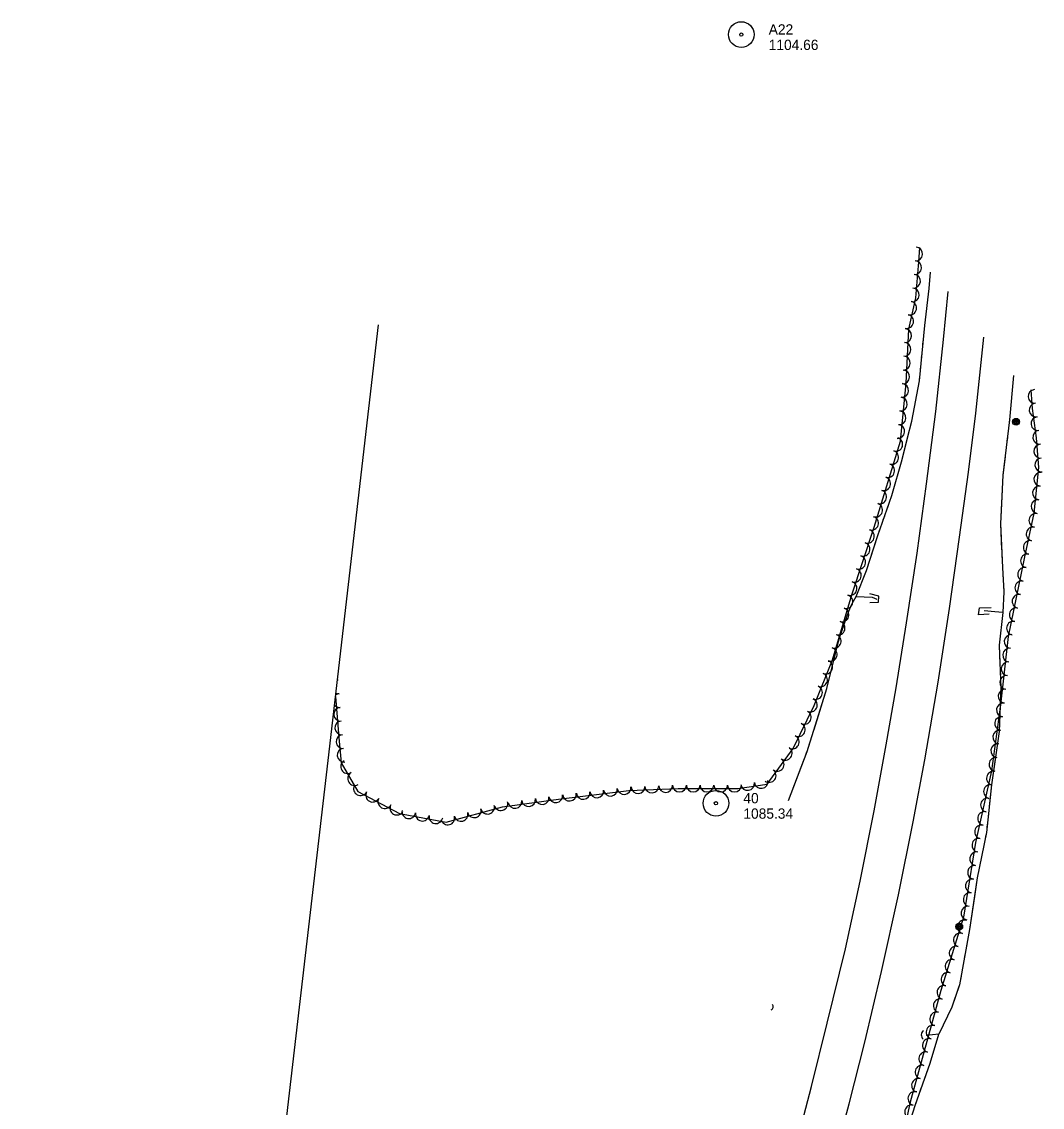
# Model space of a CAD drawing. Extents: x 296807 to 298965, y 28597 to 31038.
# Drawn here: x 297186 to 297782, y 30405 to 31038 of the extents above; entities that cross this region are included whole.
import ezdxf

# ---------------------------------------------------------------- set-up
doc = ezdxf.new("R2010")
doc.units = 0
for name, color, linetype in [('Level 11', 7, 'Continuous'), ('Level 14', 7, 'Continuous'), ('Level 15', 7, 'Continuous'), ('Level 18', 7, 'Continuous'), ('Level 19', 7, 'Continuous'), ('Level 4', 7, 'Continuous'), ('Level 6', 7, 'Continuous')]:
    doc.layers.add(name, color=color, linetype=linetype)

msp = doc.modelspace()

# ---------------------------------------------------------------- linework, layer by layer
at = {"layer": 'Level 11'}
for points in [[(297635.16, 30371.8), (297647.12, 30416.96), (297656.29, 30453.93), (297666.9, 30497.33), (297675.45, 30536.82), (297683.72, 30577.83), (297690.69, 30616.35), (297696.51, 30649.69), (297702.5, 30687.56), (297708.83, 30728.12), (297714.29, 30768.62), (297719.57, 30810.81), (297724.1, 30852.77), (297726.91, 30880.84)], [(297660.56, 30374.97), (297669.04, 30406.87), (297678.19, 30442.96), (297687.99, 30484.12), (297697.88, 30528.81), (297706.45, 30571.48), (297713.28, 30607.61), (297720.96, 30652.98), (297727.58, 30695.82), (297733.46, 30737.44), (297738.69, 30775.35), (297742.95, 30809.84), (297747.72, 30854.12)]]:
    msp.add_lwpolyline(points, dxfattribs=at)
at = {"layer": 'Level 14'}
for centre, radius in [((297766.5, 30804.81), 2.02), ((297766.49, 30804.82), 1.52), ((297766.53, 30804.81), 1.01), ((297766.52, 30804.82), 0.502), ((297733.29, 30510.29), 2.02), ((297733.27, 30510.29), 1.52), ((297733.31, 30510.28), 1.01), ((297733.31, 30510.29), 0.502)]:
    msp.add_circle(centre, radius, dxfattribs=at)
at = {"layer": 'Level 15'}
for points in [[(297681.1, 30699.33), (297686.22, 30699.53), (297686.38, 30703.14), (297681.19, 30704.42)], [(297750.69, 30692.62), (297744.59, 30692.16), (297745.13, 30696.2), (297751.9, 30696.46)]]:
    msp.add_lwpolyline(points, dxfattribs=at)
for centre, radius, start, end in [((297622.78, 30463.62), 1.99, 293.25773, 39.49729), ((297714.14, 30447.03), 2.99, 123.25084, 229.4904)]:
    msp.add_arc(centre, radius, start, end, dxfattribs=at)
at = {"layer": 'Level 18'}
for points in [[(297369.42, 30644.59), (297371.36, 30620.72), (297372.64, 30605.9), (297382.43, 30589.19), (297406.71, 30576.23), (297433.85, 30571.25), (297466.81, 30580.19), (297499.42, 30584.74), (297540.53, 30589.63), (297569.33, 30590.83), (297604.2, 30590.83), (297621.32, 30593.4), (297636.36, 30614.26), (297648.64, 30639.23), (297659.28, 30665.88), (297670.65, 30703.96), (297683.68, 30743.31), (297699.02, 30793.47), (297702.27, 30827.34), (297703.83, 30858.88), (297707.9, 30877.13), (297709.73, 30898.1), (297710.33, 30906.57)], [(297775.12, 30823.44), (297775.96, 30812.53), (297778.18, 30795.42), (297779.49, 30778.12), (297776.76, 30751.45), (297771.24, 30724.98), (297761.79, 30679.57), (297757.4, 30639.7), (297752.04, 30601.17), (297742.85, 30559.38), (297735.87, 30515.74), (297722.52, 30473.14), (297704.63, 30407.83), (297695.4, 30365.61)]]:
    msp.add_lwpolyline(points, dxfattribs=at)
for centre, start, end in [((297707.95, 30902.71), 265.9557, 85.94038), ((297707.33, 30894.75), 265.03014, 85.01482), ((297706.63, 30886.75), 265.03014, 85.01482), ((297705.93, 30878.76), 265.03014, 85.01482), ((297704.42, 30871.17), 257.41837, 77.40305), ((297702.67, 30863.34), 257.41837, 77.40305), ((297701.53, 30855.06), 267.17606, 87.16074), ((297701.14, 30847.05), 267.17606, 87.16074), ((297700.74, 30839.03), 267.17606, 87.16074), ((297700.34, 30831.02), 267.17606, 87.16074), ((297699.75, 30823.12), 264.52646, 84.51114), ((297777.52, 30819.6), 94.41641, 274.40109), ((297698.98, 30815.13), 264.52646, 84.51114), ((297698.22, 30807.14), 264.52646, 84.51114), ((297778.18, 30811.72), 97.39956, 277.38424), ((297779.22, 30803.76), 97.39956, 277.38424), ((297697.45, 30799.15), 264.52646, 84.51114), ((297780.25, 30795.8), 97.39956, 277.38424), ((297696.27, 30791.67), 253.01054, 72.99522), ((297780.87, 30787.69), 94.33369, 274.31837), ((297693.92, 30784), 253.01054, 72.99522), ((297691.58, 30776.33), 253.01054, 72.99522), ((297781.48, 30779.69), 94.33369, 274.31837), ((297689.23, 30768.65), 253.01054, 72.99522), ((297780.91, 30771.33), 84.16735, 264.15202), ((297780.09, 30763.34), 84.16735, 264.15202), ((297686.89, 30760.98), 253.01054, 72.99522), ((297779.27, 30755.36), 84.16735, 264.15202), ((297684.54, 30753.3), 253.01054, 72.99522), ((297682.2, 30745.63), 253.01054, 72.99522), ((297778.03, 30747.23), 78.23315, 258.21783), ((297679.73, 30738.05), 251.67937, 71.66405), ((297776.39, 30739.37), 78.23315, 258.21783), ((297677.2, 30730.43), 251.67937, 71.66405), ((297774.75, 30731.51), 78.23315, 258.21783), ((297773.11, 30723.66), 78.24295, 258.22763), ((297674.68, 30722.81), 251.67937, 71.66405), ((297672.16, 30715.19), 251.67937, 71.66405), ((297771.48, 30715.8), 78.24295, 258.22763), ((297669.63, 30707.57), 251.67937, 71.66405), ((297769.84, 30707.95), 78.24295, 258.22763), ((297667.23, 30699.85), 253.38132, 73.36599), ((297768.21, 30700.09), 78.24295, 258.22763), ((297664.93, 30692.16), 253.38132, 73.36599), ((297766.57, 30692.24), 78.24295, 258.22763), ((297662.64, 30684.48), 253.38132, 73.36599), ((297764.93, 30684.38), 78.24295, 258.22763), ((297660.34, 30676.79), 253.38132, 73.36599), ((297763.58, 30676.68), 83.72284, 263.70752), ((297658.04, 30669.1), 253.38132, 73.36599), ((297762.7, 30668.71), 83.72284, 263.70752), ((297655.36, 30661.74), 248.25631, 68.24099), ((297761.82, 30660.73), 83.72284, 263.70752), ((297652.39, 30654.29), 248.25631, 68.24099), ((297371.07, 30650.2), 94.65433, 97.77653), ((297760.95, 30652.75), 83.72284, 263.70752), ((297371.72, 30642.2), 94.65433, 123.05587), ((297371.07, 30650.2), 249.03068, 274.63901), ((297649.42, 30646.83), 248.25631, 68.24099), ((297760.07, 30644.78), 83.72284, 263.70752), ((297371.72, 30642.2), 223.75134, 274.63901), ((297646.46, 30639.55), 243.81561, 63.80029), ((297759.11, 30636.75), 82.08919, 262.07387), ((297372.37, 30634.2), 94.65433, 274.63901), ((297642.92, 30632.35), 243.81561, 63.80029), ((297758, 30628.8), 82.08919, 262.07387), ((297373.02, 30626.2), 94.65433, 274.63901), ((297639.38, 30625.15), 243.81561, 63.80029), ((297373.68, 30618.22), 94.94953, 274.93421), ((297635.83, 30617.95), 243.81561, 63.80029), ((297756.89, 30620.85), 82.08919, 262.07387), ((297374.37, 30610.22), 94.94953, 274.93421), ((297631.76, 30611.47), 234.21335, 54.19803), ((297755.79, 30612.91), 82.08919, 262.07387), ((297627.07, 30604.97), 234.21335, 54.19803), ((297754.68, 30604.96), 82.08919, 262.07387), ((297376.41, 30603.63), 120.37676, 300.36143), ((297622.38, 30598.46), 234.21335, 54.19803), ((297753.25, 30596.9), 77.60927, 257.59394), ((297380.47, 30596.7), 120.37676, 300.36143), ((297617.74, 30594.99), 188.52812, 8.51279), ((297383.91, 30590.79), 151.89782, 331.8825), ((297390.99, 30587.01), 151.89782, 331.8825), ((297513.85, 30588.57), 186.7897, 6.77438), ((297521.82, 30589.52), 186.7897, 6.77438), ((297529.78, 30590.47), 186.7897, 6.77438), ((297537.75, 30591.42), 186.7897, 6.77438), ((297545.92, 30591.96), 182.39361, 2.37828), ((297553.93, 30592.29), 182.39361, 2.37828), ((297561.95, 30592.63), 182.39361, 2.37828), ((297570.06, 30592.93), 180.01095, 359.99563), ((297578.08, 30592.93), 180.01095, 359.99563), ((297586.11, 30592.93), 180.01095, 359.99563), ((297594.13, 30592.93), 180.01095, 359.99563), ((297602.16, 30592.93), 180.01095, 359.99563), ((297609.8, 30593.8), 188.52812, 8.51279), ((297751.53, 30589.07), 77.60927, 257.59394), ((297398.07, 30583.22), 151.89782, 331.8825), ((297465.83, 30582.1), 195.18582, 15.1705), ((297474.03, 30583.32), 187.95638, 7.94106), ((297481.98, 30584.43), 187.95638, 7.94106), ((297489.92, 30585.54), 187.95638, 7.94106), ((297497.87, 30586.65), 187.95638, 7.94106), ((297505.88, 30587.63), 186.7897, 6.77438), ((297749.8, 30581.23), 77.60927, 257.59394), ((297405.14, 30579.44), 151.89782, 331.8825), ((297412.13, 30577.37), 169.61424, 349.59892), ((297420.03, 30575.92), 169.61424, 349.59892), ((297442.6, 30575.8), 195.18582, 15.1705), ((297450.34, 30577.9), 195.18582, 15.1705), ((297458.09, 30580), 195.18582, 15.1705), ((297748.08, 30573.39), 77.60927, 257.59394), ((297427.92, 30574.47), 169.61424, 349.59892), ((297434.85, 30573.7), 195.18582, 15.1705), ((297746.36, 30565.55), 77.60927, 257.59394), ((297744.73, 30557.82), 80.92286, 260.90754), ((297743.46, 30549.9), 80.92286, 260.90754), ((297742.19, 30541.97), 80.92286, 260.90754), ((297740.93, 30534.05), 80.92286, 260.90754), ((297739.66, 30526.13), 80.92286, 260.90754), ((297738.39, 30518.2), 80.92286, 260.90754), ((297736.32, 30510.16), 72.60266, 252.58733), ((297733.92, 30502.5), 72.60266, 252.58733), ((297731.52, 30494.84), 72.60266, 252.58733), ((297729.12, 30487.18), 72.60266, 252.58733), ((297726.72, 30479.53), 72.60266, 252.58733), ((297724.36, 30471.94), 74.6905, 254.67518), ((297722.24, 30464.2), 74.6905, 254.67518), ((297720.12, 30456.46), 74.6905, 254.67518), ((297718, 30448.72), 74.6905, 254.67518), ((297715.89, 30440.98), 74.6905, 254.67518), ((297713.77, 30433.24), 74.6905, 254.67518), ((297711.65, 30425.5), 74.6905, 254.67518), ((297709.53, 30417.76), 74.6905, 254.67518), ((297707.41, 30410.02), 74.6905, 254.67518), ((297705.57, 30402.32), 77.67699, 257.66167)]:
    msp.add_arc(centre, 4.01, start, end, dxfattribs=at)
at = {"layer": 'Level 19'}
for points in [[(297673.12, 30702.98), (297679.23, 30718.14), (297685.76, 30738.4), (297694, 30761.85), (297699.95, 30782.84), (297705.68, 30805.25), (297710.03, 30828.77), (297713.18, 30861.02), (297715.77, 30882.54), (297716.57, 30892.1)], [(297712.77, 30856.89), (297713.18, 30861.02), (297715.77, 30882.54), (297716.57, 30892.1)], [(297712.06, 30849.6), (297712.3, 30852.03)], [(297711.35, 30842.31), (297711.59, 30844.74)], [(297710.64, 30835.02), (297710.88, 30837.45)], [(297703.18, 30795.47), (297705.68, 30805.25), (297710.03, 30828.77), (297710.16, 30830.15)], [(297765.03, 30831.88), (297762.68, 30805.9), (297758.73, 30773.69), (297757.33, 30745.22), (297758.54, 30719.88), (297759.24, 30705.65), (297758.8, 30693.56), (297753.99, 30693.95), (297747.79, 30694.55)], [(297765.03, 30831.88), (297762.68, 30805.9), (297762.54, 30804.79)], [(297762.09, 30801.07), (297761.86, 30799.2)], [(297693.84, 30761.38), (297694, 30761.85), (297699.95, 30782.84), (297703.18, 30795.47)], [(297761.4, 30795.48), (297761.17, 30793.62)], [(297760.72, 30789.89), (297760.49, 30788.03)], [(297760.03, 30784.3), (297758.73, 30773.69), (297757.92, 30757.24)], [(297691.42, 30754.5), (297692.23, 30756.79)], [(297757.92, 30757.24), (297757.33, 30745.22), (297758.05, 30730.15)], [(297689, 30747.63), (297689.81, 30749.92)], [(297686.59, 30740.75), (297687.39, 30743.04)], [(297673.12, 30702.98), (297679.23, 30718.14), (297685.04, 30736.15)], [(297758.23, 30726.42), (297758.32, 30724.55)], [(297758.5, 30720.82), (297758.54, 30719.88), (297758.59, 30718.95)], [(297758.77, 30715.22), (297758.86, 30713.36)], [(297759.05, 30709.63), (297759.24, 30705.65), (297758.8, 30693.56), (297753.99, 30693.95), (297747.79, 30694.55)], [(297633.74, 30583.97), (297644.6, 30612.56), (297655.97, 30649.15), (297663.46, 30678.8), (297668.79, 30694.29), (297670.89, 30698.9), (297673.12, 30702.98), (297682.58, 30702.55), (297685.29, 30701.41)], [(297667.85, 30691.56), (297668.79, 30694.29), (297670.89, 30698.9), (297673.12, 30702.98), (297682.58, 30702.55), (297685.29, 30701.41)], [(297758.8, 30693.56), (297756.61, 30674.53), (297757.63, 30649.31), (297756.62, 30624.23), (297752.17, 30593.04), (297749.16, 30565.19), (297743.87, 30538.86), (297739.31, 30508.71), (297733.43, 30476.28), (297729.03, 30463.28), (297721.43, 30447.48)], [(297758.8, 30693.56), (297756.61, 30674.53), (297757.05, 30663.49)], [(297664.49, 30681.79), (297665.05, 30683.42)], [(297666.17, 30686.68), (297666.73, 30688.3)], [(297662.97, 30676.85), (297663.39, 30678.53)], [(297656, 30649.25), (297662.12, 30673.51)], [(297757.22, 30659.33), (297757.31, 30657.25)], [(297757.48, 30653.08), (297757.56, 30651)], [(297648.58, 30625.36), (297655.97, 30649.15), (297656, 30649.25)], [(297757.53, 30646.83), (297757.45, 30644.75)], [(297757.28, 30640.58), (297756.62, 30624.23), (297754.66, 30610.46)], [(297647.04, 30620.42), (297647.56, 30622.07)], [(297645.51, 30615.48), (297646.02, 30617.13)], [(297633.74, 30583.97), (297642.62, 30607.35)], [(297643.85, 30610.58), (297644.46, 30612.19)], [(297754.66, 30610.46), (297752.17, 30593.04), (297750.81, 30580.42)], [(297750.36, 30576.27), (297750.13, 30574.19)], [(297749.68, 30570.04), (297749.46, 30567.96)], [(297748.89, 30563.83), (297748.47, 30561.78)], [(297747.65, 30557.68), (297743.87, 30538.86), (297742.21, 30527.87)], [(297742.21, 30527.87), (297739.31, 30508.71), (297737.36, 30497.95)], [(297736.61, 30493.84), (297736.24, 30491.78)], [(297735.49, 30487.67), (297735.12, 30485.61)], [(297734.37, 30481.5), (297734, 30479.44)], [(297733.11, 30475.36), (297729.03, 30463.28), (297721.43, 30447.48)], [(297647.8, 30274.42), (297665.2, 30311.43), (297681.24, 30338.46), (297698.28, 30376.88), (297707.78, 30406.57), (297716.33, 30430.57), (297721.43, 30447.48), (297713.98, 30446.89)], [(297712.83, 30420.73), (297716.33, 30430.57), (297721.43, 30447.48), (297713.98, 30446.89)], [(297710.36, 30413.8), (297711.18, 30416.11)], [(297707.89, 30406.87), (297708.71, 30409.18)]]:
    msp.add_lwpolyline(points, dxfattribs=at)
at = {"layer": 'Level 4'}
msp.add_lwpolyline([(297186.21, 29936.92), (297336.94, 30366.3), (297365.1, 30607.27), (297394.48, 30861.31)], dxfattribs=at)
at = {"layer": 'Level 6'}
for centre, radius in [((297606.14, 31030.72), 7.5), ((297606.14, 31030.72), 0.96), ((297591.35, 30582.26), 7.5), ((297591.35, 30582.26), 0.96)]:
    msp.add_circle(centre, radius, dxfattribs=at)

# ---------------------------------------------------------------- texts
for s, p in [('A22', (297622.14, 31030.72)), ('1104.66', (297622.14, 31021.72)), ('40', (297607.35, 30582.26)), ('1085.34', (297607.35, 30573.26))]:
    msp.add_text(s, height=6, dxfattribs=at).set_placement(p)

doc.saveas('drawing.dxf')
